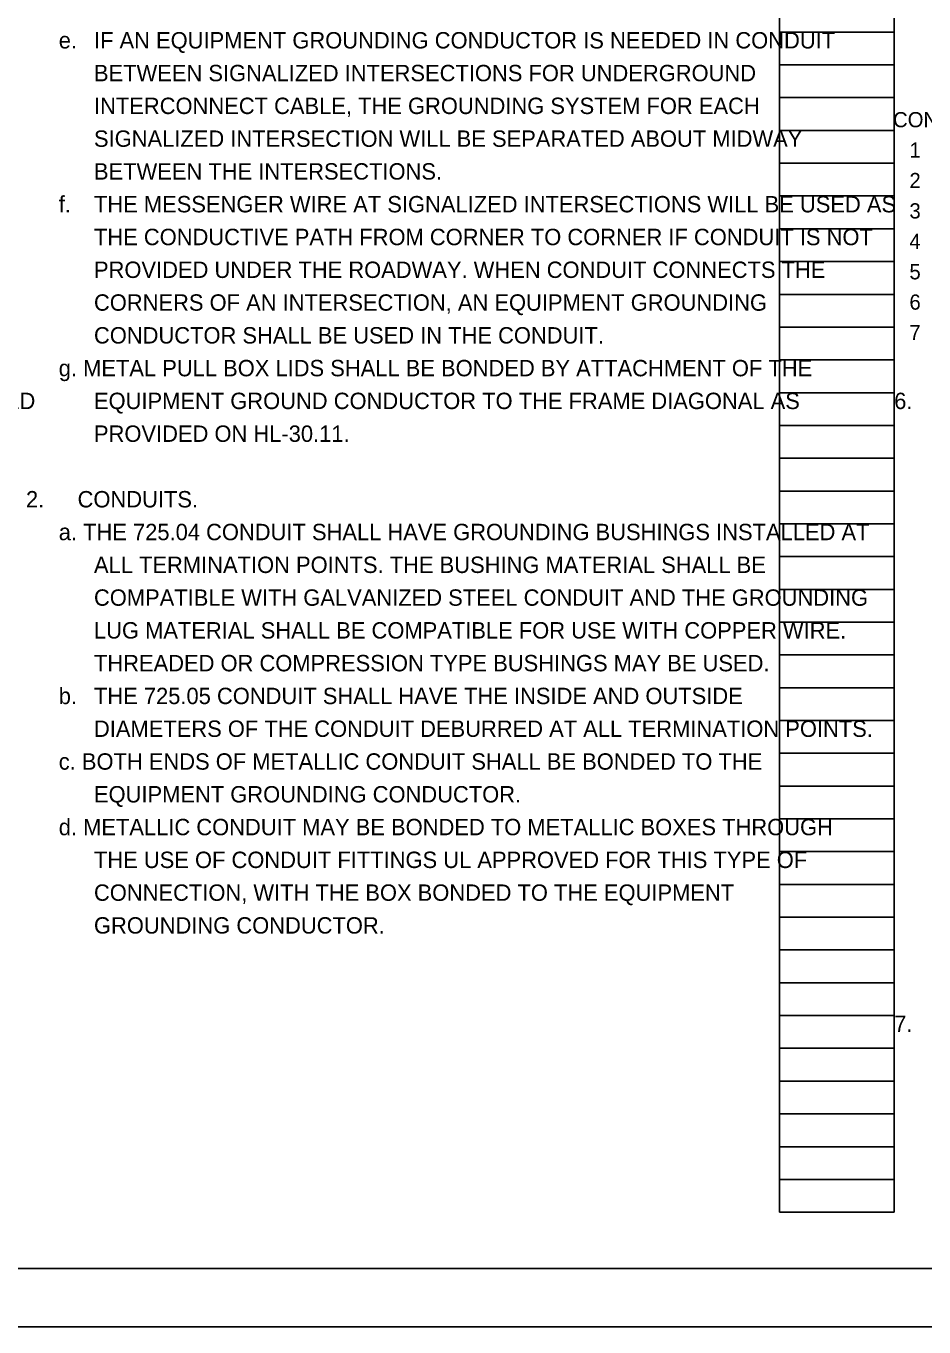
# Model space of a CAD drawing. Extents: x 0 to 34, y -30 to 22.
# Drawn here: x 17.24 to 24.91, y 0 to 11.11 of the extents above; entities that cross this region are included whole.
import ezdxf

# ---------------------------------------------------------------- set-up
doc = ezdxf.new("R2010")
doc.units = 0
for name, color, linetype in [('SH_Border', 7, 'Continuous'), ('SH_Cut_Line', 7, 'Continuous'), ('SH_Data', 7, 'Continuous'), ('SH_Text', 7, 'Continuous')]:
    doc.layers.add(name, color=color, linetype=linetype)

msp = doc.modelspace()

# ---------------------------------------------------------------- linework, layer by layer
at = {"layer": 'SH_Border'}
msp.add_lwpolyline([(1.5, 21.5), (33.5, 21.5), (33.5, 0.5), (1.5, 0.5)], close=True, dxfattribs=at)
at = {"layer": 'SH_Cut_Line'}
msp.add_lwpolyline([(0, 0), (34, 0), (34, 22), (0, 22)], close=True, dxfattribs=at)
at = {"layer": 'SH_Data'}
for p, q in [((23.68, 0.98), (23.68, 21.14)), ((24.66, 0.98), (24.66, 21.14)), ((23.68, 11.06), (24.66, 11.06)), ((23.68, 10.78), (24.66, 10.78)), ((23.68, 10.5), (24.66, 10.5)), ((23.68, 10.22), (24.66, 10.22)), ((23.68, 9.94), (24.66, 9.94)), ((23.68, 9.66), (24.66, 9.66)), ((23.68, 9.38), (24.66, 9.38)), ((23.68, 9.1), (24.66, 9.1)), ((23.68, 8.82), (24.66, 8.82)), ((23.68, 8.54), (24.66, 8.54)), ((23.68, 8.26), (24.66, 8.26)), ((23.68, 7.98), (24.66, 7.98)), ((23.68, 7.7), (24.66, 7.7)), ((23.68, 7.42), (24.66, 7.42)), ((23.68, 7.14), (24.66, 7.14)), ((23.68, 6.86), (24.66, 6.86)), ((23.68, 6.58), (24.66, 6.58)), ((23.68, 6.3), (24.66, 6.3)), ((23.68, 6.02), (24.66, 6.02)), ((23.68, 5.74), (24.66, 5.74)), ((23.68, 5.46), (24.66, 5.46)), ((23.68, 5.18), (24.66, 5.18)), ((23.68, 4.9), (24.66, 4.9)), ((23.68, 4.62), (24.66, 4.62)), ((23.68, 4.34), (24.66, 4.34)), ((23.68, 4.06), (24.66, 4.06)), ((23.68, 3.78), (24.66, 3.78)), ((23.68, 3.5), (24.66, 3.5)), ((23.68, 3.22), (24.66, 3.22)), ((23.68, 2.94), (24.66, 2.94)), ((23.68, 2.66), (24.66, 2.66)), ((23.68, 2.38), (24.66, 2.38)), ((23.68, 2.1), (24.66, 2.1)), ((23.68, 1.82), (24.66, 1.82)), ((23.68, 1.54), (24.66, 1.54)), ((23.68, 1.26), (24.66, 1.26)), ((23.68, 0.98), (24.66, 0.98))]:
    msp.add_line(p, q, dxfattribs=at)

# ---------------------------------------------------------------- texts
at = {"layer": 'SH_Text'}
for s, height, p in [('e.', 0.14, (17.52, 10.92)), ('IF AN EQUIPMENT GROUNDING CONDUCTOR IS NEEDED IN CONDUIT ', 0.14, (17.821, 10.92)), ('BETWEEN SIGNALIZED INTERSECTIONS FOR UNDERGROUND ', 0.14, (17.821, 10.64)), ('INTERCONNECT CABLE, THE GROUNDING SYSTEM FOR EACH ', 0.14, (17.821, 10.36)), ('COND. NO', 0.1298, (24.65, 10.247)), ('SIGNALIZED INTERSECTION WILL BE SEPARATED ABOUT MIDWAY ', 0.14, (17.821, 10.08)), ('1', 0.13, (24.79, 9.987)), ('BETWEEN THE INTERSECTIONS.', 0.14, (17.821, 9.8)), ('2', 0.13, (24.79, 9.727)), ('f.', 0.14, (17.52, 9.52)), ('THE MESSENGER WIRE AT SIGNALIZED INTERSECTIONS WILL BE USED AS ', 0.14, (17.821, 9.52)), ('3', 0.13, (24.79, 9.468)), ('THE CONDUCTIVE PATH FROM CORNER TO CORNER IF CONDUIT IS NOT ', 0.14, (17.821, 9.24)), ('4', 0.13, (24.79, 9.208)), ('PROVIDED UNDER THE ROADWAY. WHEN CONDUIT CONNECTS THE ', 0.14, (17.821, 8.96)), ('5', 0.13, (24.79, 8.948)), ('CORNERS OF AN INTERSECTION, AN EQUIPMENT GROUNDING ', 0.14, (17.821, 8.68)), ('6', 0.13, (24.79, 8.689)), ('7', 0.13, (24.79, 8.429)), ('CONDUCTOR SHALL BE USED IN THE CONDUIT.', 0.14, (17.821, 8.4)), ('g. METAL PULL BOX LIDS SHALL BE BONDED BY ATTACHMENT OF THE ', 0.14, (17.52, 8.12)), ('WHICH SHALL BE PROTECTED BY OFF-DUTY CITY OF LYNDHURST POLICE, HIRED ', 0.14, (9.82, 7.84)), ('EQUIPMENT GROUND CONDUCTOR TO THE FRAME DIAGONAL AS ', 0.14, (17.821, 7.84)), ('6.', 0.14, (24.66, 7.84)), ('PROVIDED ON HL-30.11.', 0.14, (17.821, 7.56)), ('2.', 0.14, (17.24, 7)), ('CONDUITS.', 0.14, (17.681, 7)), ('a. THE 725.04 CONDUIT SHALL HAVE GROUNDING BUSHINGS INSTALLED AT ', 0.14, (17.52, 6.72)), ('ALL TERMINATION POINTS. THE BUSHING MATERIAL SHALL BE ', 0.14, (17.821, 6.44)), ('COMPATIBLE WITH GALVANIZED STEEL CONDUIT AND THE GROUNDING ', 0.14, (17.821, 6.16)), ('LUG MATERIAL SHALL BE COMPATIBLE FOR USE WITH COPPER WIRE. ', 0.14, (17.821, 5.88)), ('THREADED OR COMPRESSION TYPE BUSHINGS MAY BE USED.', 0.14, (17.821, 5.6)), ('b.', 0.14, (17.52, 5.32)), ('THE 725.05 CONDUIT SHALL HAVE THE INSIDE AND OUTSIDE ', 0.14, (17.821, 5.32)), ('DIAMETERS OF THE CONDUIT DEBURRED AT ALL TERMINATION POINTS.', 0.14, (17.821, 5.04)), ('c. BOTH ENDS OF METALLIC CONDUIT SHALL BE BONDED TO THE ', 0.14, (17.52, 4.76)), ('EQUIPMENT GROUNDING CONDUCTOR.', 0.14, (17.821, 4.48)), ('d. METALLIC CONDUIT MAY BE BONDED TO METALLIC BOXES THROUGH ', 0.14, (17.52, 4.2)), ('THE USE OF CONDUIT FITTINGS UL APPROVED FOR THIS TYPE OF ', 0.14, (17.821, 3.92)), ('CONNECTION, WITH THE BOX BONDED TO THE EQUIPMENT ', 0.14, (17.821, 3.64)), ('GROUNDING CONDUCTOR.', 0.14, (17.821, 3.36)), ('7.', 0.14, (24.66, 2.52))]:
    msp.add_text(s, height=height, dxfattribs=at).set_placement(p)

doc.saveas('drawing.dxf')
